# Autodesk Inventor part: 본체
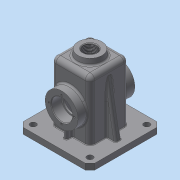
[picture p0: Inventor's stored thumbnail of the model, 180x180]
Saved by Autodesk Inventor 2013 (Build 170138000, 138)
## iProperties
Created: 2018-10
Part Number: 본체
Material: 일반
Document SubType Name: Modeling
Designer: Administrator
Density: 1 g/cm^3
Author: Administrator
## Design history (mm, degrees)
sketch "스케치1"
  geometry: L1 (-32.5, 32.5)-(32.5, 32.5); L2 (32.5, 32.5)-(32.5, -32.5); L3 (32.5, -32.5)-(-32.5, -32.5); L4 (-32.5, -32.5)-(-32.5, 32.5); L5 (-32.5, 32.5)-(32.5, -32.5); L6 (32.5, 32.5)-(-32.5, -32.5); 1 further point
  constraints: 12 end point, 2 midpoint, 2 parallel, 1 horizontal, 1 perpendicular
  dimensions: "d0" = 65 distance of L2.end L3.end; "d1" = 65 distance of L1.end L2.end
extrude "돌출1" new body sketch "스케치1" distance "d2" = 110; taper "d3" = 0 deg
sketch "스케치2"
  geometry: L1 (-27.5, 27.5)-(27.5, 27.5); L2 (27.5, 27.5)-(27.5, -27.5); L3 (27.5, -27.5)-(-27.5, -27.5); L4 (-27.5, -27.5)-(-27.5, 27.5); L5 (-27.5, 27.5)-(27.5, -27.5); L6 (27.5, 27.5)-(-27.5, -27.5); 1 further point
  constraints: 12 end point, 2 midpoint, 2 parallel, 1 horizontal, 1 perpendicular
  dimensions: "d4" = 55 distance of L2.end L3.end; "d5" = 55 distance of L1.end L2.end
extrude "돌출2" cut sketch "스케치2" distance "d6" = 105; taper "d7" = 0 deg
sketch "스케치3"
  geometry: L1 (32.5, 32.5)-(-32.5, 32.5) reference; L2 (-32.5, 32.5)-(-32.5, -32.5) reference; L3 (-32.5, -32.5)-(32.5, -32.5) reference; L4 (32.5, -32.5)-(32.5, 32.5) reference; L5 (-60, 60)-(60, 60); L6 (60, 60)-(60, -60); L7 (60, -60)-(-60, -60); L8 (-60, -60)-(-60, 60); L9 (-60, 60)-(60, -60); L10 (60, 60)-(-60, -60); 1 further point
  constraints: 12 end point, 2 midpoint, 2 parallel, 1 horizontal, 1 perpendicular
  dimensions: "d8" = 120 distance of L6.end L7.end; "d9" = 120 distance of L5.end L6.end
extrude "돌출3" join sketch "스케치3" distance "d10" = 10; taper "d11" = 0 deg
sketch "스케치4"
  geometry: L1 (27.5, 0)-(27.5, 105) reference; L2 (27.5, 105)-(-27.5, 105) reference; L3 (-27.5, 105)-(-27.5, 0) reference; L4 (-27.5, 0)-(-60, 0) reference; L5 (-60, 0)-(-60, 10) reference; L6 (-60, 10)-(-32.5, 10) reference; L7 (-32.5, 10)-(-32.5, 110) reference; L8 (-32.5, 110)-(32.5, 110) reference; L9 (32.5, 110)-(32.5, 10) reference; L10 (32.5, 10)-(60, 10) reference; L11 (60, 10)-(60, 0) reference; L12 (60, 0)-(27.5, 0) reference; L13 (-84, 0)-(84, 0) reference; L14 (0, -26)-(0, 156) reference; L15 (0, 110)-(0, 120); L16 (0, 120)-(20, 120); L17 (20, 120)-(21.228, 110); L18 (20, 120)-(35, 120); L19 (21.228, 110)-(0, 110); 1 further point
  constraints: 10 end point, 3 point on line, 2 perpendicular, 1 horizontal, 1 midpoint
  dimensions: "d13" = 10 distance of L15.start L15.end; "d14" = 20 distance of L15.end L16.end; "d16" = 83 deg angle of L17 L18
revolve "회전1" sketch "스케치4" stored, may be unused: angle "d17" = 90 deg
sketch "스케치5"
  geometry: L1 (92.5, -100)-(92.5, -110) reference; L2 (92.5, -110)-(-27.5, -110) reference; L3 (-27.5, -110)-(-27.5, -100) reference; L4 (-27.5, -100)-(0, -100) reference; L5 (0, -100)-(65, -100) reference; L6 (65, -100)-(92.5, -100) reference; L7 (0, -100)-(0, 0) reference; L8 (0, 0)-(65, 0) reference; L9 (65, 0)-(65, -100) reference; L10 (32.5, -144)-(32.5, 24) reference; L11 (-51.5, -110)-(116.5, -110) reference; C1 r 27.5 at (32.5, -55); 1 further point
  constraints: 1 centre point, 1 point on line
  dimensions: "d18" = 55 diameter of C1; "d19" = 55 distance from line of L2 C1.centre
extrude "돌출4" join sketch "스케치5" distance "d20" = 15; taper "d21" = 0 deg
sketch "스케치6"
  geometry: C1 r 27.5 at (0, 0) reference; C2 r 17.5 at (0, 0); 1 further point
  constraints: 1 centre point, 1 coincident
  dimensions: "d22" = 35 diameter of C2
extrude "돌출5" cut sketch "스케치6" distance "d23" = 17; taper "d24" = 0 deg
sketch "스케치7"
  geometry: C1 r 17.5 at (0, 0) reference; C2 r 15 at (0, 0); 1 further point
  constraints: 1 centre point, 1 coincident
  dimensions: "d25" = 30 diameter of C2
extrude "돌출6" cut sketch "스케치7" distance "d26" = 3; taper "d27" = 0 deg
sketch "스케치8" dims "d28" = 42
  geometry: L1 (0, 0)-(0, 21); C1 r 27.5 at (0, 0) reference; 1 further point
  constraints: 2 end point, 1 coincident, 1 vertical, 1 vertical alignment, 2 other
hole "구멍1" sketch "스케치8" at (0, 21) diameter "d29" = 3.242; stored, may be unused: countersink angle "d33" = 90 deg, drill point angle "d35" = 118 deg; dims "d30" = 8, "d31" = 4, "d32" = 2, "d34" = 10
sketch "스케치9"
  geometry: L1 (27.5, 0)-(27.5, 105) reference; L2 (27.5, 105)-(-27.5, 105) reference; L3 (-27.5, 105)-(-27.5, 0) reference; L4 (-27.5, 0)-(-60, 0) reference; L5 (-60, 0)-(-60, 10) reference; L6 (-60, 10)-(-32.5, 10) reference; L7 (-32.5, 10)-(-32.5, 110) reference; L8 (-32.5, 110)-(-21.228, 110) reference; L9 (-21.228, 110)-(-20, 120) reference; L10 (-20, 120)-(20, 120) reference; L11 (20, 120)-(21.228, 110) reference; L12 (21.228, 110)-(32.5, 110) reference; L13 (32.5, 110)-(32.5, 10) reference; L14 (32.5, 10)-(60, 10) reference; L15 (60, 10)-(60, 0) reference; L16 (60, 0)-(27.5, 0) reference; L17 (-84, 0)-(84, 0) reference; L18 (0, -24)-(0, 144) reference; L19 (48, 10)-(32.5, 97.905); 1 further point
  constraints: 2 end point, 2 point on line
  dimensions: "d39" = 12 distance from line of L15 L19.start; "d40" = 10 deg angle of L19 L15
feature "리브1" sketch "스케치9" dims "d41" = 1, "d42" = 10, "d43" = 0, "d44" = 0, "d45" = 1, "d46" = 1
hole "구멍2" diameter "d49" = 22.835; stored, may be unused: countersink angle "d53" = 90 deg, drill point angle "d55" = 118 deg; dims "d47" = 10, "d48" = 10, "d50" = 100, "d51" = 4, "d52" = 2, "d54" = 10
fillet "모깎기1" dims "d56" = 8
fillet "모깎기2" dims "d57" = 8
fillet "모깎기3" dims "d58" = 8
fillet "모깎기4" dims "d59" = 3
chamfer "모따기1" distance "d60" = 1; stored, may be unused: second distance "d61" = 2, angle "d62" = 45 deg
chamfer "모따기2" distance "d63" = 1; stored, may be unused: second distance "d64" = 2, angle "d65" = 45 deg
sketch "스케치10"
  geometry: L1 (70, -30.5)-(70, -27.5) reference; L2 (70, -27.5)-(105, -27.5) reference; L3 (105, -27.5)-(105, -11.418) reference; L4 (105, -11.418)-(119, -11.418) reference; L5 (119, -11.418)-(120, -12.418) reference; L6 (120, -12.418)-(120, -20) reference; L7 (120, -20)-(112.634, -20.904) reference; L8 (110, -23.882)-(110, -24.5) reference; L9 (102, -32.5)-(82.5, -32.5) reference; L10 (82.5, -32.5)-(82.5, -47.5) reference; L11 (82.5, -47.5)-(77.621, -47.5) reference; L12 (77.621, -47.5)-(77.621, -37.5) reference; L13 (77.621, -37.5)-(76, -36.526) reference; L14 (76, -36.526)-(74.379, -37.5) reference; L15 (74.379, -37.5)-(74.379, -47.5) reference; L16 (74.379, -47.5)-(73.5, -47.5) reference; L17 (73.5, -47.5)-(72.5, -46.5) reference; L18 (72.5, -46.5)-(72.5, -30.5) reference; L19 (72.5, -30.5)-(70, -30.5) reference; L20 (40, -27.5)-(40, -30.5) reference; L21 (40, -30.5)-(37.5, -30.5) reference; L22 (37.5, -30.5)-(37.5, -46.5) reference; L23 (37.5, -46.5)-(36.5, -47.5) reference; L24 (36.5, -47.5)-(35.621, -47.5) reference; L25 (35.621, -47.5)-(35.621, -37.5) reference; L26 (35.621, -37.5)-(34, -36.526) reference; L27 (34, -36.526)-(32.379, -37.5) reference; L28 (32.379, -37.5)-(32.379, -47.5) reference; L29 (32.379, -47.5)-(27.5, -47.5) reference; L30 (27.5, -47.5)-(27.5, -32.5) reference; L31 (27.5, -32.5)-(10, -32.5) reference; L32 (10, -32.5)-(10, -60) reference; L33 (10, -60)-(0, -60) reference; L34 (0, -60)-(0, -27.5) reference; L35 (0, -27.5)-(40, -27.5) reference; L36 (70, 27.5)-(70, 30.5) reference; L37 (70, 30.5)-(72.5, 30.5) reference; L38 (72.5, 30.5)-(72.5, 46.5) reference; L39 (72.5, 46.5)-(73.5, 47.5) reference; L40 (73.5, 47.5)-(74.379, 47.5) reference; L41 (74.379, 47.5)-(74.379, 37.5) reference; L42 (74.379, 37.5)-(76, 36.526) reference; L43 (76, 36.526)-(77.621, 37.5) reference; L44 (77.621, 37.5)-(77.621, 47.5) reference; L45 (77.621, 47.5)-(82.5, 47.5) reference; L46 (82.5, 47.5)-(82.5, 32.5) reference; L47 (82.5, 32.5)-(102, 32.5) reference; L48 (110, 24.5)-(110, 23.882) reference; L49 (112.634, 20.904)-(120, 20) reference; L50 (120, 20)-(120, 12.418) reference; L51 (120, 12.418)-(119, 11.418) reference; L52 (119, 11.418)-(105, 11.418) reference; L53 (105, 11.418)-(105, 27.5) reference; L54 (105, 27.5)-(70, 27.5) reference; L55 (40, 30.5)-(40, 27.5) reference; L56 (40, 27.5)-(0, 27.5) reference; L57 (0, 27.5)-(0, 60) reference; L58 (0, 60)-(10, 60) reference; L59 (10, 60)-(10, 32.5) reference; L60 (10, 32.5)-(27.5, 32.5) reference; L61 (27.5, 32.5)-(27.5, 47.5) reference; L62 (27.5, 47.5)-(32.379, 47.5) reference; L63 (32.379, 47.5)-(32.379, 37.5) reference; L64 (32.379, 37.5)-(34, 36.526) reference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; A1 r 3 centre (113, -23.882) between (112.634, -20.904) and (110, -23.882) reference; A2 r 8 centre (102, -24.5) between (102, -32.5) and (110, -24.5) reference; A3 r 8 centre (102, 24.5) between (110, 24.5) and (102, 32.5) reference; A4 r 3 centre (113, 23.882) between (110, 23.882) and (112.634, 20.904) reference; 1 further point
  constraints: 2 end point, 2 point on line, 1 perpendicular
  dimensions: "d66" = 15 distance between parallel lines of L73 L56
feature "리브2" sketch "스케치10" dims "d68" = 1, "d69" = 6, "d70" = 0, "d71" = 0, "d72" = 1, "d73" = 1
sketch "스케치11"
  geometry: L1 (-47.5, 47.5)-(47.5, 47.5); L2 (47.5, 47.5)-(47.5, -47.5); L3 (47.5, -47.5)-(-47.5, -47.5); L4 (-47.5, -47.5)-(-47.5, 47.5); L5 (-47.5, 47.5)-(47.5, -47.5); L6 (47.5, 47.5)-(-47.5, -47.5); 1 further point
  constraints: 12 end point, 2 midpoint, 2 parallel, 1 horizontal, 1 perpendicular
  dimensions: "d74" = 95 distance of L2.end L3.end; "d75" = 95 distance of L1.end L2.end
hole "구멍3" sketch "스케치11" at (-47.5, 47.5) diameter "d76" = 10; stored, may be unused: countersink angle "d80" = 90 deg, drill point angle "d82" = 118 deg; dims "d77" = 6, "d78" = 4, "d79" = 2, "d81" = 8
chamfer "모따기3" distance "d83" = 8; stored, may be unused: second distance "d84" = 2, angle "d85" = 45 deg
fillet "모깎기5" dims "d86" = 3
fillet "모깎기6" dims "d87" = 3
fillet "모깎기7" dims "d88" = 3
fillet "모깎기8" dims "d89" = 3
fillet "모깎기9" dims "d90" = 3
fillet "모깎기10" dims "d91" = 3
fillet "모깎기11" dims "d92" = 3
fillet "모깎기12" dims "d93" = 1
sketch "스케치12"
  geometry: L1 (-8, 0)-(-8, -91) reference; L2 (4.5, 18)-(44.5, 18) reference; 2 further points
  constraints: 1 other
  dimensions: "d94" = 32.5 distance from line of L1 point (24.5, -8); "d95" = 26 distance from line of L2 point (24.5, -8)
feature "엠보싱1" sketch "스케치12" dims "d96" = 0.5, "d97" = 0
fillet "모깎기13" dims "d98" = 3
fillet "모깎기14" dims "d99" = 3
node "솔리드1"
mirror "대칭1"
mirror "대칭2"
mirror "대칭3"
pattern_circular "원형 패턴1" dims angle "d37" = 360 deg
mirror "대칭4"
mirror "대칭5"
mirror "대칭6"
mirror "대칭7"
mirror "대칭8"
node "절단 모서리 투영1"
node "절단 모서리 투영2"
node "절단 모서리 투영3"
node "절단 모서리 투영4"
